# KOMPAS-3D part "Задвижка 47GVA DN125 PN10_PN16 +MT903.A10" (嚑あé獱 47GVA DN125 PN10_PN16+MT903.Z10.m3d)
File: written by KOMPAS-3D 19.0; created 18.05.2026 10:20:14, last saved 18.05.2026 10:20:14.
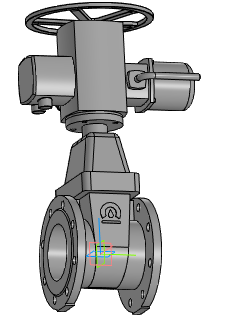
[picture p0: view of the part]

Document properties: Автор: Энергия; Полное имя файла: ..\Задвижка 47GVA DN50_DN1000+MT903.Z\Задвижка 47GVA DN125 PN10_PN16+MT903.Z10.a3d

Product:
- Part/product: Задвижка 47GVA DN125 PN10_PN16 +MT903.A10
    Масса: 94.9723
  - Body: Электропривод MT903.Z05-15
      Масса: 49.8062
  - Body: Задвижка 47GVA DN125 PN10_PN16 без исполнит. мех.
      Масса: 45.1661

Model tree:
1. Операция без истории:1
2. Операция без истории:2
